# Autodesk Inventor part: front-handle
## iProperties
Author: Administrator
Created: 2001-01
Part Number: front-handle
Document SubType Name: Modeling
Designer: Administrator
Control State: 0
Master: False
Checked Out: False
PropertySet Name: Design Tracking Control
Shininess: 0.0
PropertySet Name: _Private Model Information
Density: 0.0
Volumn: 0.0
Area: 0.0
PropertySet Name: Model Information
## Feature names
1. Revolution1
2. Hole1
